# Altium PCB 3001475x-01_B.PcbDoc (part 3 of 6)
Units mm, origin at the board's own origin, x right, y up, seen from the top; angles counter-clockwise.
Board outline 335 x 91 mm, 12 copper layers (Top Layer, L2 GND, Layer 3, L4 GND, Layer 5, L6 PWR, L7 3V3, Layer 8, L9 GND, Layer 10, L11 GND, Bottom Layer), stack 1.59 mm thick; 339 components, 431 nets, 1732 pads, 1526 vias.
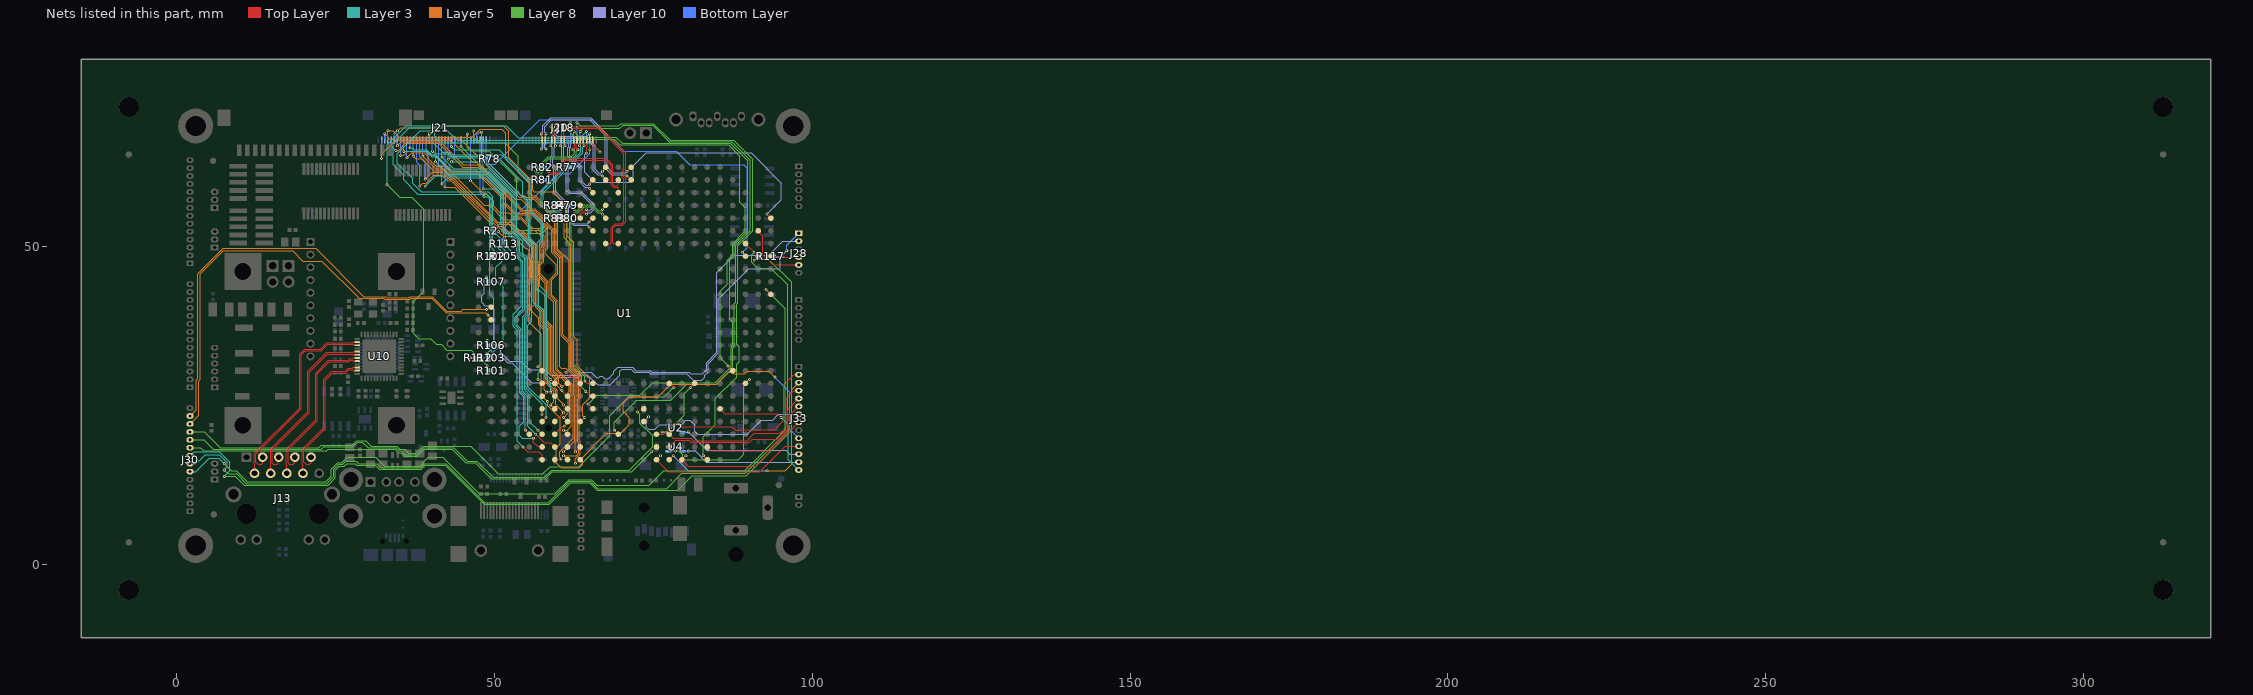
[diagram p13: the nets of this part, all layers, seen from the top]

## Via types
v1: diameter 0.45, hole 0.2, Top Layer to Bottom Layer, 1511 vias
v2: diameter 0.5, hole 0.2, Top Layer to Bottom Layer, 14 vias
v3: diameter 0.45/0.45/0.45/0.45/0.45/0.45/0.45/0.45/0.45/0.45/0.45/0.45 (per signal layer), hole 0.2, Top Layer to Bottom Layer, 1 vias

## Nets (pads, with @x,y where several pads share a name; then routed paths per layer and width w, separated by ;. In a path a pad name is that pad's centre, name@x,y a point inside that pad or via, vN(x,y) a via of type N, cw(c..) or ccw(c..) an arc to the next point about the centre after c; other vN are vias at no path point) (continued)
CSI1_D13: J33.2 U1.AB15 | length 30.2
  Top Layer w0.125: U1.AB15@75.5,20.5 75.538,20.462 76.546,20.462 77.996,21.913 79.087,21.913 79.288,21.712 87.288,21.712 87.875,21.125 89,21.125 89.062,21.187 94.062,21.187 95.552,22.677 95.552,28.302 97.125,29.875 J33.2@97.875,29.875
CSI1_D14: J33.3 U1.AD16 | length 34.2
  Top Layer w0.125: U1.AD16@77.5,16.5 v1(78.125,17.125)
  Layer 5 w0.125: v1(92.875,14.75) 95.75,14.75 96.75,15.75 96.75,27.5 J33.3@97.875,28.625
  Layer 10 w0.125: v1(78.125,17.125) 80.5,14.75 v1(92.875,14.75)
CSI1_D15: J33.4 U1.AB16 | length 26.7
  Top Layer w0.125: U1.AB16@77.5,20.5 78.132,19.868 80.882,19.868 81.25,19.5 89.75,19.5 90.875,20.625 94.875,20.625 95.875,21.625 95.875,26.125 97.125,27.375 J33.4@97.875,27.375
CSI1_D16: J33.5 U1.AC16 | length 25.5
  Top Layer w0.125: U1.AC16@77.5,18.5 78.538,19.538 80.671,19.538 80.958,19.25 90.125,19.25 90.552,19.677 94.427,19.677 96.125,21.375 96.125,24.375 J33.5@97.875,26.125
CSI1_D17: J33.6 U1.AC19 | length 18.8
  Top Layer w0.125: U1.AC19@83.5,18.5 84.132,17.868 92.993,17.868 96.375,21.25 96.375,23.375 J33.6@97.875,24.875
CSI1_D18: J33.7 U1.AA14 | length 30.4
  Top Layer w0.125: U1.AA14@73.5,22.5 v1(74.25,23.25)
  Layer 10 w0.125: v1(74.25,23.25) 73.875,22.875 73.875,21.625 74.25,21.25 75.25,21.25 76,22 79.413,22 80.125,22.712 80.75,22.712 81.5,21.962 81.5,21 82,20.5 89.75,20.5 91.962,22.712 93.75,22.712 94.663,23.625 J33.7@97.875,23.625
CSI1_D19: J33.8 U1.AD17 | length 22.5
  Top Layer w0.125: v1(80.125,17.125) U1.AD17@79.5,16.5 80.5,15.5 91,15.5 J33.8@97.875,22.375
CSI1_HSYNC: J33.12 U2.3 | length 19.7
  Layer 10 w0.125: v1(80.5,20.875) 83.375,18 95.875,18 96.5,17.375 J33.12@97.875,17.375
  Bottom Layer w0.125: U2.3@79.6,20.85 v1@80.475,20.85
CSI1_HSYNC/BTCFG2_3: U1.V18 U2.4 | length 11.3
  Top Layer w0.125: v1(80.875,27.875) U1.V18@81.5,28.5
  Layer 8 w0.125: v1(76.375,20.875) 77.25,20.875 79.875,23.5 79.875,26.875 v1(80.875,27.875)
  Bottom Layer w0.125: v1@76.4,20.85 U2.4@77.4,20.85
CSI1_MCLK: J33.10 R2.2 | length 99.1
  Layer 5 w0.125: v1(50.625,52.375) 51.375,51.625 53,51.625 54.875,49.75 55.125,49.75 55.5,49.375 55.5,38.125 57.375,36.25 57.375,26.625 v1(58.375,25.625) 58.375,25 60.375,23 60.375,19 59.75,18.375 59.75,16 60.5,15.25 63.375,15.25 63.875,15.75 63.875,16.875 67.625,20.625 69.896,20.625 71.25,21.979 71.25,23.125 70.25,24.125 70.25,25.375 71.25,26.375 75.75,26.375 77.75,28.375 84.875,28.375 86.75,30.25 87.375,30.25 87.625,30 89.375,30 89.75,30.375 93.25,30.375 v1(94.125,29.5)
  Bottom Layer w0.125: R2.2@50.105,52.375 v1(50.625,52.375) ; v1(94.125,29.5) 96.5,27.125 96.5,21.25 J33.10@97.875,19.875
CSI1_PIXCLK: J33.11 U1.AD15 | length 25.7
  Top Layer w0.125: v1(76.125,17.125) U1.AD15@75.5,16.5 77.375,14.625 91.75,14.625 95.75,18.625 J33.11@97.875,18.625
CSI1_RESET_N: J33.14 U1.Y20 | length 19.6
  Top Layer w0.125: U1.Y20@85.5,24.5 86.25,23.75 94.5,23.75 v1(95.125,23.125)
  Layer 3 w0.125: v1(95.125,23.125) 96.25,22 96.25,16.5 J33.14@97.875,14.875
CSI1_VSYNC: J33.13 U4.3 | length 19
  Layer 10 w0.125: v1(80.5,17.875) 81.625,17.875 82.462,17.038 82.462,16.954 83.292,16.125 J33.13@97.875,16.125
  Bottom Layer w0.125: U4.3@79.6,17.85 v1@80.475,17.85
CSI1_VSYNC/BTCFG2_4: U1.V22 U4.4 | length 26.1
  Top Layer w0.125: U1.V22@89.5,28.5 v1(90.125,29.125)
  Layer 8 w0.125: v1(78.5,17.875) 79,17.875 79.625,17.25 79.625,16.75 79.875,16.5 88.396,16.5 89.25,17.354 89.25,28.25 v1(90.125,29.125)
  Bottom Layer w0.125: U4.4@77.425,17.875 v1(78.5,17.875)
CSI_CLK0_N: J20.15 U1.B11 | length 17.1
  Top Layer w0.122: v1(58.875,68.875) 59.122,68.628 59.122,67.372 59,67.25 J20.15@59,66.8 ; v1(67,61.125) U1.B11@67.5,60.5
  Layer 10 w0.101: v1(58.875,68.875) 59.1,68.65 59.1,67.726 59.751,67.075 64.251,67.075 65.538,65.788 65.538,62.063 66.251,61.35 66.775,61.35 v1(67,61.125)
CSI_CLK0_P: J20.14 U1.A11 | length 16.6
  Top Layer w0.122: J20.14@59.5,66.8 59.5,67.25 59.377,67.373 59.377,68.628 v1(59.625,68.875) ; v1(67,61.875) U1.A11@67.5,62.5
  Layer 10 w0.101: v1(59.625,68.875) 59.4,68.65 59.4,67.85 59.875,67.375 64.375,67.375 65.838,65.912 65.838,62.187 66.375,61.65 66.775,61.65 v1(67,61.875)
CSI_D0_N: J20.12 U1.G12 | length 30.2
  Top Layer w0.122: J20.12@60.5,66.8 60.5,67.448 60.622,67.57 60.622,68.358 61.139,68.875 66.5,68.875 70.63,64.745 70.63,62.255 70.38,62.005 70.38,60.981 70.63,60.731 70.63,53.899 70.106,53.375 69.125,53.375 68.621,52.871 68.621,50.629 68.75,50.5 U1.G12@69.5,50.5
CSI_D0_P: J20.11 U1.G11 | length 29.3
  Top Layer w0.122: J20.11@61,66.8 61,67.448 60.877,67.57 60.877,68.253 61.245,68.62 66.394,68.62 70.375,64.639 70.375,62.361 70.125,62.111 70.125,60.875 70.375,60.625 70.375,54.005 70,53.63 69.019,53.63 68.366,52.977 68.366,50.629 68.237,50.5 U1.G11@67.5,50.5
CSI_D1_N: J20.18 U1.A13 | length 23.7
  Top Layer w0.122: v1(57.375,67.75) 57.5,67.625 J20.18@57.5,66.8 ; v1(70.875,61.875) U1.A13@71.5,62.5
  Layer 10 w0.101: v1(57.375,67.75) 57.6,67.975 57.6,68.999 58.851,70.25 65.125,70.25 67.75,67.625 67.75,62.5 68.6,61.65 70.65,61.65 v1(70.875,61.875)
CSI_D1_P: J20.17 U1.B13 | length 23.2
  Top Layer w0.122: J20.17@58,66.8 58,67.625 v1(58.125,67.75) ; v1(70.875,61.125) U1.B13@71.5,60.5
  Layer 10 w0.101: v1(58.125,67.75) 57.9,67.975 57.9,68.875 58.975,69.95 65.001,69.95 67.45,67.501 67.45,62.376 68.476,61.35 70.65,61.35 v1(70.875,61.125)
CSI_D2_N: R82.1 U1.B12 | length 17.7
  Top Layer w0.122: v1(58.5,61.875) 58.747,61.628 59.875,61.628 60.375,62.128 60.375,63.111 61.144,63.88 67.606,63.88 68.625,62.861 68.625,59.875 68.872,59.628 69.378,59.628 69.5,59.75 U1.B12@69.5,60.5
  Bottom Layer w0.122: R82.1@57.98,62.5 v1(58.5,61.875)
CSI_D2_P: R81.1 U1.C12 | length 17.7
  Top Layer w0.122: v1(58.5,61.125) 58.747,61.373 59.981,61.373 60.63,62.022 60.63,63.005 61.25,63.625 67.5,63.625 68.37,62.755 68.37,59.769 68.767,59.372 69.378,59.372 69.5,59.25 U1.C12@69.5,58.5
  Bottom Layer w0.122: R81.1@57.98,60.5 v1(58.5,61.125)
CSI_D3_N: R80.1 U1.E11 | length 7.1
  Top Layer w0.122: v1(67,55.125) U1.E11@67.5,54.5
  Layer 8 w0.101: v1(62.5,55.125) 62.725,55.35 63.149,55.35 64.124,56.325 65.251,56.325 66.226,55.35 66.775,55.35 v1(67,55.125)
  Bottom Layer w0.122: R80.1@61.98,54.5 v1(62.5,55.125)
CSI_D3_P: R79.1 U1.D11 | length 7.1
  Top Layer w0.122: v1(67,55.875) U1.D11@67.5,56.5
  Layer 8 w0.101: v1(62.5,55.875) 62.725,55.65 63.025,55.65 64,56.625 65.375,56.625 66.35,55.65 66.775,55.65 v1(67,55.875)
  Bottom Layer w0.122: R79.1@61.98,56.5 v1(62.5,55.875)
CSI_I2C_SCL: J20.2 R112.2 | length 88
  Top Layer w0.125: J20.2@65.5,66.8 65.5,66 v1(66.625,64.875)
  Layer 3 w0.125: v1(46.25,32.5) 48.875,32.5 51.375,35 51.375,43.6 50.25,44.725 50.25,46.75 51.25,47.75 51.25,49.125 49.75,50.625 49.75,57.875 49,58.625 38.5,58.625 37.125,60 37.125,60.75 34.75,63.125 34.75,64.625 38.375,68.25 40.25,68.25 40.625,67.875 40.625,67.25 41.5,66.375 65.125,66.375 v1(66.625,64.875)
  Bottom Layer w0.125: v1(46.25,32.5) R112.2@47.02,32.5
CSI_I2C_SDA: J20.3 R113.2 | length 22.5
  Top Layer w0.125: v1(65,65.25) J20.3@65,66.8
  Bottom Layer w0.125: R113.2@51.5,50.98 51.5,53 60,61.5 61.875,61.5 65,64.625 v1(65,65.25)
CSI_RESET_N: J20.4 U1.E24 | length 48.6
  Top Layer w0.125: v1(64.5,64.75) 64.5,65.5 64.625,65.625 64.625,66 64.5,66.125 J20.4@64.5,66.8 ; v1(92.875,55.125) U1.E24@93.5,54.5
  Layer 10 w0.125: v1(64.5,64.75) 64.25,64.5 64.25,61.75 65.875,60.125 71.25,60.125 71.875,60.75 71.875,62.75 73.875,64.75 90.375,64.75 95.125,60 95.125,57.375 v1(92.875,55.125)
CSID2_N: J20.8 R82.2 | length 11.3
  Top Layer w0.122: v1(62.375,65.25) 62.622,65.497 62.622,66.253 62.5,66.375 J20.8@62.5,66.8
  Layer 8 w0.101: v1(56.5,61.875) 56.725,61.65 57,61.65 57.375,62.025 57.375,63.049 58.451,64.125 62.125,64.125 62.6,64.6 62.6,65.025 v1(62.375,65.25)
  Bottom Layer w0.122: v1(56.5,61.875) R82.2@57.02,62.5
CSID2_P: J20.7 R81.2 | length 11.8
  Top Layer w0.122: J20.7@63,66.8 63,66.375 62.877,66.252 62.877,65.498 v1(63.125,65.25)
  Layer 8 w0.101: v1(56.5,61.125) 56.725,61.35 57.124,61.35 57.675,61.901 57.675,62.925 58.575,63.825 62.249,63.825 62.9,64.476 62.9,65.025 v1(63.125,65.25)
  Bottom Layer w0.122: v1(56.5,61.125) R81.2@57.02,60.5
CSID3_N: J20.6 R80.2 R83.2 | length 18.4
  Top Layer w0.122: v1(63.375,65.875) 63.5,66 J20.6@63.5,66.8
  Layer 3 w0.101: v1(60.5,55.125) 60.275,55.35 58.476,55.35 57.375,56.451 57.375,58.65 63.6,64.875 63.6,65.65 v1(63.375,65.875)
  Bottom Layer w0.122: R83.2@59.98,54.5 v1(60.5,55.125) R80.2@61.02,54.5
CSID3_P: J20.5 R79.2 R84.2 | length 17.9
  Top Layer w0.122: J20.5@64,66.8 64,66 v1(64.125,65.875)
  Layer 3 w0.101: v1(60.5,55.875) 60.275,55.65 58.6,55.65 57.675,56.575 57.675,58.526 63.9,64.751 63.9,65.65 v1(64.125,65.875)
  Bottom Layer w0.122: R84.2@59.98,56.5 v1(60.5,55.875) R79.2@61.02,56.5
DISP0_CLK: J21.27 U1.V9 | length 54.6
  Top Layer w0.125: v1(61.25,30.25) 62,29.5 62.5,29.5 U1.V9@63.5,28.5
  Layer 8 w0.125: v1(44.75,65.75) 51.75,58.75 51.75,54 53.625,52.125 57.5,52.125 58.5,53.125 58.5,53.875 59,54.375 60.875,54.375 61.375,53.875 61.375,50.75 61.75,50.375 61.75,30.75 v1(61.25,30.25)
  Bottom Layer w0.125: v1(44.75,65.75) J21.27@44.75,66.8
DISP0_CONTRAST: J21.32 U1.AD8 | length 63.2
  Top Layer w0.125: v1(60.875,17.125) U1.AD8@61.5,16.5
  Layer 5 w0.125: v1(48,68) 48,64.25 54.25,58 54.75,58 55,57.75 56.375,57.75 60,54.125 60,49.625 61.75,47.875 61.75,35.5 62.25,35 62.25,30.957 63.25,29.957 63.25,26.25 63.125,26.125 63.125,19.25 63.25,19.125 63.25,17.5 62.875,17.125 v1(60.875,17.125)
  Bottom Layer w0.125: J21.32@47.25,66.8 47.25,67.625 47.625,68 v1(48,68)
DISP0_DAT0: J21.2 U1.AC8 | length 76.3
  Top Layer w0.125: v1(60.875,17.75) U1.AC8@61.5,18.5
  Layer 5 w0.125: v1(32.25,63.875) 32.25,64.625 34.375,66.75 43.125,66.75 46.625,63.25 47.5,63.25 53.25,57.5 54.25,57.5 55.75,56 56.375,56 57.375,55 58.25,55 59.5,53.75 59.5,49.375 60.5,48.375 60.5,36 61.75,34.75 61.75,30.75 62.75,29.75 62.75,26.625 62.625,26.5 62.625,19.5 v1(60.875,17.75)
  Bottom Layer w0.125: v1(32.25,63.875) J21.2@32.25,66.8
DISP0_DAT1: J21.3 U1.AC9 | length 72.4
  Top Layer w0.125: v1(62.75,17.75) U1.AC9@63.5,18.5
  Layer 5 w0.125: v1(32.75,67.75) 33.5,67 44.625,67 53.875,57.75 54.625,57.75 54.875,57.5 56.25,57.5 59.75,54 59.75,49.5 60.75,48.5 60.75,36.125 62,34.875 62,30.854 63,29.854 63,26.5 62.875,26.375 62.875,19.375 62.75,19.25 v1(62.75,17.75)
  Bottom Layer w0.125: J21.3@32.75,66.8 v1(32.75,67.75)
DISP0_DAT2: J21.4 U1.AD9 | length 80
  Top Layer w0.125: v1(62.75,15.875) U1.AD9@63.5,16.5
  Layer 5 w0.125: v1(33.25,68.25) 34,68.25 35,67.25 46.5,67.25 47.75,68.5 51.125,68.5 51.75,67.875 51.75,63.75 55.5,60 55.5,58.5 56,58 56.5,58 57.864,56.636 58.364,56.636 61,54 61,51.375 62,50.375 62,35.625 62.5,35.125 62.5,31.061 63.5,30.061 63.5,26.125 63.375,26 63.375,19.5 63.5,19.375 63.5,17.375 62.75,16.625 v1(62.75,15.875)
  Bottom Layer w0.125: J21.4@33.25,66.8 v1(33.25,68.25)
DISP0_DAT3: J21.5 U1.AB8 | length 68.1
  Top Layer w0.125: v1(60.875,21.125) U1.AB8@61.5,20.5
  Layer 5 w0.125: v1(34.5,65.125) 34.875,65.125 36,66.25 41.25,66.25 45,62.5 47.375,62.5 54.375,55.5 56.125,55.5 59,52.625 59,49.125 60,48.125 60,45.979 60,45.771 59,44.771 59,42.354 59.875,41.479 59.875,30.729 62.229,28.375 62.25,28.375 62.25,26.875 62.125,26.75 62.125,21.75 61.5,21.125 v1(60.875,21.125)
  Bottom Layer w0.125: J21.5@33.75,66.8 33.75,65.875 v1(34.5,65.125)
DISP0_DAT4: J21.6 U1.AA9 | length 73.3
  Top Layer w0.125: U1.AA9@63.5,22.5 v1(64.125,23.125)
  Layer 5 w0.125: v1(34.75,68.25) 35.25,68.75 41.125,68.75 41.375,69 51.375,69 52.25,68.125 52.25,64 56,60.25 56,58.854 56.229,58.625 59.146,58.625 61.5,56.271 61.5,51.625 62.5,50.625 62.5,35.875 63,35.375 63,31.268 65,29.268 65,26.25 63.875,25.125 63.875,23.375 v1(64.125,23.125)
  Bottom Layer w0.125: J21.6@34.25,66.8 34.25,67.75 v1(34.75,68.25)
DISP0_DAT5: J21.7 U1.AD7 | length 71.3
  Top Layer w0.125: U1.AD7@59.5,16.5 v1(60.5,16.625)
  Layer 5 w0.125: v1(34.75,65.875) 35.375,66.5 41.5,66.5 45.125,62.875 47.375,62.875 54.5,55.75 56.25,55.75 59.25,52.75 59.25,49.25 60.25,48.25 60.25,31.125 60.5,30.875 61.25,30.875 62.5,29.625 62.5,26.75 62.375,26.625 62.375,19.875 60.25,17.75 60.25,16.875 v1(60.5,16.625)
  Bottom Layer w0.125: v1(34.75,65.875) J21.7@34.75,66.8
DISP0_DAT6: J21.8 U1.AB7 | length 67.4
  Top Layer w0.125: U1.AB7@59.5,20.5 60.125,21.125 60.75,21.75 v1(61,21.75)
  Layer 5 w0.125: v1(35.25,64.375) 35.75,64.375 36.375,65 39.5,65 40,64.5 40.625,64.5 43,62.125 47.125,62.125 51.75,57.5 51.75,56.875 53.375,55.25 56,55.25 58.375,52.875 58.375,49.75 58,49.375 58,48.875 59.75,47.125 59.75,45.875 58.75,44.875 58.75,42.25 59.625,41.375 59.625,30.625 62,28.25 62,27 61.875,26.875 61.875,22.625 v1(61,21.75)
  Bottom Layer w0.125: v1(35.25,64.375) J21.8@35.25,66.8
DISP0_DAT7: J21.9 U1.AC7 | length 64.9
  Top Layer w0.125: v1(56.5,20.5) 57.875,19.125 58.875,19.125 U1.AC7@59.5,18.5
  Layer 3 w0.125: v1(35.75,65) 39.25,65 40.125,64.125 40.75,64.125 43.25,61.625 49,61.625 52.75,57.875 52.75,52.25 54,51 54,49.104 55,48.104 55,39.5 54.5,39 54.5,27.25 55.25,26.5 55.25,21.75 v1(56.5,20.5)
  Bottom Layer w0.125: v1(35.75,65) J21.9@35.75,66.8
DISP0_DAT8: J21.10 U1.AA8 | length 63.6
  Top Layer w0.125: v1(60.875,23.125) U1.AA8@61.5,22.5
  Layer 5 w0.125: v1(36.25,64) 37,64.75 39,64.75 39.625,64.125 39.625,63.875 40.875,62.625 42.125,62.625 43.125,61.625 47.25,61.625 51.5,57.375 51.5,56.75 53,55.25 53.25,55 55.875,55 58.125,52.75 58.125,49.875 57.75,49.5 57.75,47.625 57.25,47.125 57.25,45.75 58.5,44.5 58.5,42.125 59.375,41.25 59.375,30.5 61.75,28.125 61.75,27.25 61.625,27.125 61.625,23.875 v1(60.875,23.125)
  Bottom Layer w0.125: v1(36.25,64) J21.10@36.25,66.8
DISP0_DAT9: J21.11 U1.AB6 | length 60.4
  Top Layer w0.125: v1(56.875,21.125) U1.AB6@57.5,20.5
  Layer 3 w0.125: v1(36.75,65.5) 37.125,65.5 37.375,65.25 39.375,65.25 40.25,64.375 40.875,64.375 43.375,61.875 49.146,61.875 53,58.021 53,52.375 54.5,50.875 54.5,49 55.25,48.25 55.25,39.375 54.75,38.875 54.75,27.5 55.5,26.75 55.5,22.5 v1(56.875,21.125)
  Bottom Layer w0.125: v1(36.75,65.5) J21.11@36.75,66.8
DISP0_DAT10: J21.12 U1.Y8 | length 55.6
  Top Layer w0.125: v1(60.875,25.125) U1.Y8@61.5,24.5
  Layer 5 w0.125: v1(37.25,64.25) 37.625,63.875 38.578,63.875 40.5,61.953 42.047,61.953 43.125,60.875 43.5,60.875 50.5,53.875 52.625,53.875 53.875,52.625 54.375,52.625 56.75,50.25 56.75,47.75 56.5,47.5 56.5,45.375 57,44.875 57,40.729 57.75,39.979 57.75,38.125 58.625,37.25 58.625,30.125 59.604,29.146 59.604,27.729 59.875,27.457 59.875,27.043 59.875,26.125 v1(60.875,25.125)
  Bottom Layer w0.125: v1@37.25,64.375 J21.12@37.25,66.8
DISP0_DAT11: J21.13 U1.Y7 | length 58.4
  Top Layer w0.125: v1(58.875,25.125) U1.Y7@59.5,24.5
  Layer 5 w0.125: v1(38.25,59.5) 38.75,60 39.25,60 40.5,61.25 41.75,61.25 42.625,60.375 43.25,60.375 50.375,53.25 51.125,53.25 52,52.375 53.375,52.375 53.625,52.125 54.146,52.125 56.25,50.021 56.25,48.125 56,47.875 56,45.125 56.5,44.625 56.5,40.5 57.25,39.75 57.25,37.875 58.125,37 58.125,28.5 59.375,27.25 59.375,25.625 v1(58.875,25.125)
  Bottom Layer w0.125: J21.13@37.75,66.8 37.75,63.25 38.25,62.75 v1(38.25,59.5)
DISP0_DAT12: J21.14 U1.AA7 | length 59.4
  Top Layer w0.125: U1.AA7@59.5,22.5 v1(60.875,23.875)
  Layer 5 w0.125: v1(39.125,60.625) 40.203,61.703 41.797,61.703 42.875,60.625 43.375,60.625 50.5,53.5 52.625,53.5 53.75,52.375 54.25,52.375 56.5,50.125 56.5,47.875 56.25,47.625 56.25,45.25 56.75,44.75 56.75,40.625 57.5,39.875 57.5,38 58.375,37.125 58.375,28.604 59.625,27.354 59.625,27.146 59.625,25.125 v1(60.875,23.875)
  Bottom Layer w0.125: J21.14@38.25,66.8 38.25,64.125 39.125,63.25 v1(39.125,60.625)
DISP0_DAT13: J21.15 U1.W8 | length 53.8
  Top Layer w0.125: v1(60.625,27.375) U1.W8@61.5,26.5
  Layer 5 w0.125: v1(38.75,64.25) 40.75,62.25 42.125,62.25 43.25,61.125 43.75,61.125 48.375,56.5 49.25,56.5 51.5,54.25 53,54.25 53.125,54.375 54.125,54.375 55.875,52.625 56.375,52.625 57.5,51.5 57.5,50 57.25,49.75 57.25,47.875 56.75,47.375 56.75,45.5 58,44.25 58,38.25 58.875,37.375 58.875,30.25 59.875,29.25 59.875,28.125 v1(60.625,27.375)
  Bottom Layer w0.125: v1@38.75,64.375 J21.15@38.75,66.8
DISP0_DAT14: J21.16 U1.AC6 | length 67.3
  Top Layer w0.125: v1(56.125,19.875) 56.125,19.25 56.875,18.5 U1.AC6@57.5,18.5
  Layer 3 w0.125: v1(39.125,59.5) 40.75,61.125 48.75,61.125 51.5,58.375 51.5,52.646 53.5,50.646 53.5,48.75 54.5,47.75 54.5,40.25 53.25,39 53.25,37.625 54,36.875 54,27 54.625,26.375 54.625,22.5 53.875,21.75 53.875,20.375 54.375,19.875 v1(56.125,19.875)
  Bottom Layer w0.125: v1(39.125,59.5) 39.625,60 39.625,64.5 39.25,64.875 J21.16@39.25,66.8
DISP0_DAT15: J21.17 U1.W7 | length 56.1
  Top Layer w0.125: v1(58.875,27.125) U1.W7@59.5,26.5
  Layer 3 w0.125: v1(39.75,67.75) 39.75,67 41.875,64.875 42.875,64.875 43.25,64.5 51.125,64.5 55.625,60 55.625,55.375 57.375,53.625 57.375,51.25 56.75,50.625 56.75,43.5 58,42.25 58,29.375 58.875,28.5 v1(58.875,27.125)
  Bottom Layer w0.125: J21.17@39.75,66.8 v1(39.75,67.75)
DISP0_DAT16: J21.18 U1.V6 | length 51.7
  Top Layer w0.125: v1(56.875,29.125) U1.V6@57.5,28.5
  Layer 3 w0.125: v1(40.25,65) 40.625,64.625 42.625,64.625 43,64.25 50.375,64.25 54.5,60.125 54.5,58.125 55.25,57.375 55.25,54.375 55.625,54 55.625,51.25 56.5,50.375 56.5,43.396 57,42.896 57,40.75 57.75,40 57.75,31 56.875,30.125 v1(56.875,29.125)
  Bottom Layer w0.125: v1(40.25,65) J21.18@40.25,66.8
DISP0_DAT17: J21.19 U1.AB5 | length 57
  Top Layer w0.125: v1(54.875,21.125) U1.AB5@55.5,20.5
  Layer 3 w0.125: v1(40.75,63.375) 42.75,61.375 48.875,61.375 51.75,58.5 51.75,52.75 53.75,50.75 53.75,49 54.75,48 54.75,40.125 53.587,38.962 53.587,37.663 54.25,37 54.25,27.125 54.875,26.5 v1(54.875,21.125)
  Bottom Layer w0.125: v1(40.75,63.375) J21.19@40.75,66.8
DISP0_DAT18: J21.20 U1.AD6 | length 64.5
  Top Layer w0.125: v1(54.5,18.5) 55.25,17.75 57,17.75 57.5,17.25 U1.AD6@57.5,16.5
  Layer 3 w0.125: v1(41.75,59.875) 42.75,60.875 48.646,60.875 51.25,58.271 51.25,52.5 51.75,52 51.75,50.125 54.25,47.625 54.25,40.625 53,39.375 53,37.5 53.625,36.875 53.625,19.375 v1(54.5,18.5)
  Bottom Layer w0.125: J21.20@41.25,66.8 41.25,62.75 41.75,62.25 v1(41.75,59.875)
DISP0_DAT19: J21.21 U1.Y6 | length 54.3
  Top Layer w0.125: v1(57.5,23.625) U1.Y6@57.5,24.5
  Layer 3 w0.125: v1(41.75,64.125) 43.625,62.25 49.125,62.25 53.25,58.125 53.25,52.5 55.587,50.163 55.587,39.337 55,38.75 55,27.75 57.5,25.25 v1(57.5,23.625)
  Bottom Layer w0.125: v1(41.75,64.125) J21.21@41.75,66.8
DISP0_DAT20: J21.22 U1.W6 | length 50.4
  Top Layer w0.125: U1.W6@57.5,26.5 v1(58.25,27.125)
  Layer 5 w0.125: v1(42.25,59.375) 43.75,59.375 50.125,53 50.75,53 51.625,52.125 53.25,52.125 53.5,51.875 54,51.875 56,49.875 56,48.375 55.75,48.125 55.75,45 56.25,44.5 56.25,40.875 55.75,40.375 55.75,40 57,38.75 57,37.75 57.875,36.875 57.875,27.5 v1(58.25,27.125)
  Bottom Layer w0.125: v1(42.25,59.375) J21.22@42.25,66.8
DISP0_DAT21: J21.23 U1.U6 | length 46.3
  Top Layer w0.125: v1(56.875,31.125) U1.U6@57.5,30.5
  Layer 3 w0.125: v1(42.75,63.75) 43,64 48.25,64 55,57.25 55,54.25 55.375,53.875 55.375,51.125 56.125,50.375 56.125,41.25 57.25,40.125 57.25,31.5 v1(56.875,31.125)
  Bottom Layer w0.125: v1(42.75,63.75) J21.23@42.75,66.8
DISP0_DAT22: J21.24 U1.V7 | length 49.5
  Top Layer w0.125: v1(58.875,29.125) U1.V7@59.5,28.5
  Layer 3 w0.125: v1(43.25,65.75) 43.75,65.25 50.75,65.25 55.875,60.125 55.875,55.5 57.625,53.75 57.625,51.125 57.125,50.625 57.125,43.875 58.25,42.75 58.25,29.75 v1(58.875,29.125)
  Bottom Layer w0.125: v1(43.25,65.75) J21.24@43.25,66.8
DISP0_DAT23: J21.25 U1.AA6 | length 54.5
  Top Layer w0.125: U1.AA6@57.5,22.5 v1(58.125,23.125)
  Layer 3 w0.125: v1(43.25,63.375) 48.375,63.375 53.5,58.25 53.5,52.625 55.837,50.288 55.837,39.954 55.912,39.879 55.912,38.301 55.25,37.638 55.25,28 58.125,25.125 v1(58.125,23.125)
  Bottom Layer w0.125: v1(43.25,63.375) 43.75,63.875 J21.25@43.75,66.8
DISP0_DRDY: J21.31 U1.V10 | length 60.6
  Top Layer w0.125: v1(64.25,28.875) 64.625,28.5 U1.V10@65.5,28.5
  Layer 8 w0.125: v1(46.75,68.25) 46.75,67.25 47.625,66.375 51.625,66.375 53.75,64.25 53.75,61.875 55.5,60.125 55.5,53.125 55.75,52.875 57.25,52.875 57.75,53.375 57.75,54.375 59.913,56.538 60.962,56.538 61.5,56 61.5,54.875 62.087,54.288 62.087,51.101 62.375,50.813 62.375,31.5 64.25,29.625 v1(64.25,28.875)
  Bottom Layer w0.125: J21.31@46.75,66.8 v1(46.75,68.25)
DISP0_HSYNC: J21.29 U1.W10 | length 62.1
  Top Layer w0.125: v1(64.375,27.25) U1.W10@65.5,26.5
  Layer 8 w0.125: v1(45.75,67.75) 45.75,65.625 46.25,65.125 49.125,65.125 53.5,60.75 53.5,52.979 53.854,52.625 57.375,52.625 58,53.25 58,54.25 60.038,56.288 60.859,56.288 61.25,55.896 61.25,54.75 61.837,54.163 61.837,50.997 62.125,50.71 62.125,31.25 63.75,29.625 63.75,27.875 v1(64.375,27.25)
  Bottom Layer w0.125: J21.29@45.75,66.8 v1(45.75,67.75)
DISP0_I2C_SCL: J21.33 R103.2 | length 35.7
  Layer 3 w0.125: v1(48.375,57.875) 48.875,57.875 49.25,57.5 49.25,42.625 49.875,42 49.875,34.25 v1(48.875,33.25)
  Bottom Layer w0.125: J21.33@47.75,66.8 47.75,58.5 v1(48.375,57.875) ; R103.2@48.875,32.645 v1(48.875,33.25)
DISP0_I2C_SDA: J21.34 R105.2 | length 22.1
  Layer 3 w0.125: v1(48.25,59.125) 50.043,59.125 51,58.168 51,53.75 50.125,52.875 50.125,52.125 51.25,51 51.25,49.875 v1(52.25,48.875)
  Bottom Layer w0.125: v1(48.25,59.125) J21.34@48.25,66.8 ; R105.2@51.52,48.875 v1(52.25,48.875)
DISP0_IRQ_N: J21.35 R78.2 U1.H22 | length 65
  Top Layer w0.125: v1(89,49.125) U1.H22@89.5,48.5
  Bottom Layer w0.125: R78.2@48.75,63.895 J21.35@48.75,66.8 ; R78.2@48.77,63.875 48.77,63.23 49,63 50.125,63 57.125,70 65.375,70 70.375,65 78.625,65 80.75,62.875 89.25,62.875 89.75,62.375 89.75,49.875 v1(89,49.125)
DISP0_VSYNC: J21.30 U1.V8 | length 48.6
  Top Layer w0.125: v1(60.625,28) U1.V8@61.5,28.5
  Layer 5 w0.125: v1(46.25,60.375) 48.25,58.375 48.625,58.375 49.875,57.125 49.875,56.375 50.875,55.375 52.375,55.375 53,54.75 54.125,54.75 56,52.875 56.625,52.875 57.875,51.625 57.875,50 57.5,49.625 57.5,47.75 57,47.25 57,45.625 58.25,44.375 58.25,38.375 59.125,37.5 59.125,30.375 60.125,29.375 60.125,28.5 v1(60.625,28)
  Bottom Layer w0.125: v1(46.25,60.375) J21.30@46.25,66.8
DSI_CLK0_N: J18.7 U1.E10 | length 18.1
  Top Layer w0.122: v1(64.875,53.875) U1.E10@65.5,54.5
  Layer 10 w0.101: v1(59.625,65.875) 59.4,65.65 59.4,64.251 59.175,64.026 59.175,62.999 59.675,62.499 59.675,58.624 61.675,56.624 61.675,54.575 62.6,53.65 64.65,53.65 v1(64.875,53.875)
  Bottom Layer w0.122: J18.7@59.5,66.8 59.5,66 v1(59.625,65.875)
DSI_CLK0_P: J18.6 U1.F10 | length 18.6
  Top Layer w0.122: v1(64.875,53.125) U1.F10@65.5,52.5
  Layer 10 w0.101: v1(58.875,65.875) 59.1,65.65 59.1,64.375 58.875,64.15 58.875,62.875 59.375,62.375 59.375,58.5 61.375,56.5 61.375,54.451 62.476,53.35 64.65,53.35 v1(64.875,53.125)
  Bottom Layer w0.122: v1(58.875,65.875) 59,66 J18.6@59,66.8
DSI_CONTRAST: J18.13 U1.Y10 | length 90.5
  Top Layer w0.125: v1(64.75,25.25) U1.Y10@65.5,24.5
  Layer 8 w0.125: v1(62.5,68.125) 63.375,67.25 69.125,67.25 70.125,66.25 87.125,66.25 89.875,63.5 89.875,52.5 87.75,50.375 87.75,48.625 87,47.875 87,38.625 87.5,38.125 87.5,34.5 87.25,34.25 87.25,31.125 84.75,28.625 74.875,28.625 72.875,26.625 66.125,26.625 v1(64.75,25.25)
  Bottom Layer w0.125: J18.13@62.5,66.8 v1(62.5,68.125)
DSI_D0_N: J18.4 U1.C10 | length 16
  Top Layer w0.122: v1(65,59.125) U1.C10@65.5,58.5
  Layer 10 w0.101: v1(58.125,65.375) 57.95,65.55 57.95,66.026 58.374,66.45 61.501,66.45 61.7,66.251 61.7,65.749 61.537,65.586 61.537,64.213 63.325,62.425 63.325,60.276 64.251,59.35 64.775,59.35 v1(65,59.125)
  Bottom Layer w0.122: J18.4@58,66.8 58,66.073 57.881,65.954 57.881,65.619 v1(58.125,65.375)
DSI_D0_P: J18.3 U1.B10 | length 16.6
  Top Layer w0.122: v1(65,59.875) U1.B10@65.5,60.5
  Layer 10 w0.101: v1(57.375,65.375) 57.55,65.55 57.55,66.05 58.25,66.75 61.625,66.75 62,66.375 62,65.625 61.837,65.462 61.837,64.337 63.625,62.549 63.625,60.4 64.375,59.65 64.775,59.65 v1(65,59.875)
  Bottom Layer w0.122: v1(57.375,65.375) 57.619,65.619 57.619,65.954 57.5,66.073 J18.3@57.5,66.8
DSI_D1_N: J18.10 U1.E9 | length 17.4
  Top Layer w0.122: U1.E9@63.5,54.5 63.5,55.25 63.619,55.369 64.256,55.369 v1(64.5,55.125)
  Layer 10 w0.101: v1(61.125,65.875) 60.9,65.65 60.9,63.35 61.625,62.625 61.625,58.924 61.874,58.675 63.624,58.675 65.675,56.624 65.675,55.901 65.124,55.35 64.725,55.35 v1(64.5,55.125)
  Bottom Layer w0.122: J18.10@61,66.8 61,66 v1(61.125,65.875)
DSI_D1_P: J18.9 U1.D9 | length 16.9
  Top Layer w0.122: U1.D9@63.5,56.5 63.5,55.766 63.635,55.631 64.256,55.631 v1(64.5,55.875)
  Layer 10 w0.101: v1(60.375,65.875) 60.6,65.65 60.6,63.226 61.325,62.501 61.325,58.8 61.75,58.375 63.5,58.375 65.375,56.5 65.375,56.025 65,55.65 64.725,55.65 v1(64.5,55.875)
  Bottom Layer w0.122: v1(60.375,65.875) 60.5,66 J18.9@60.5,66.8
DSI_I2C_SCL: J18.17 R101.2 | length 83.5
  Layer 8 w0.125: v1(33.125,59.75) 35.125,57.75 37,57.75 38.875,55.875 38.875,43 37.25,41.375 37.25,36.375 38.125,35.5 40,35.5 40.875,34.625 41.625,34.625 42.5,33.75 46.375,33.75 v1(48.875,31.25)
  Layer 3 w0.125: v1(33.125,59.75) 33.125,66 36.125,69 51.875,69 53.75,67.125 63.5,67.125 v1(64.5,68.125)
  Bottom Layer w0.125: v1(48.875,31.25) 48.875,30.645 R101.2@49.02,30.5 ; J18.17@64.5,66.8 v1(64.5,68.125)
DSI_I2C_SDA: J18.18 R102.2 | length 65.3
  Layer 3 w0.125: v1(50.375,49) 49.5,49.875 49.5,57.625 48.837,58.288 37.962,58.288 35.75,60.5 35.75,61.25 34.087,62.913 34.087,66.212 36.625,68.75 42.125,68.75 44.125,66.75 64,66.75 v1(65,67.75)
  Bottom Layer w0.125: R102.2@49.5,48.98 v1@50.355,48.98 ; J18.18@65,66.8 v1(65,67.75)
DSI_IRQ_N: J18.12 R77.2 U1.U21 | length 73.3
  Top Layer w0.125: v1(86.75,31.25) U1.U21@87.5,30.5
  Layer 8 w0.125: v1(62,69.5) 62,67.875 63,66.875 68.875,66.875 69.75,66 86.875,66 88.625,64.25 88.625,57 89.5,56.125 89.5,52.5 87.5,50.5 87.5,48.75 86.625,47.875 86.625,44.125 85.5,43 85.5,32.5 v1(86.75,31.25)
  Bottom Layer w0.125: R77.2@61.875,62.605 61.875,65.625 62,65.75 J18.12@62,66.8 v1(62,69.5)
DSI_PWR_EN: J18.15 U1.AB12 | length 88.9
  Top Layer w0.125: v1(68.875,21.125) U1.AB12@69.5,20.5
  Layer 8 w0.125: v1(63.5,68.125) 64,68.625 69.75,68.625 70.25,69.125 74.875,69.125 77.5,66.5 87.375,66.5 90.25,63.625 90.25,52.5 88,50.25 88,41.25 87.75,41 87.75,34.25 87.5,34 87.5,30.875 85,28.375 80.25,28.375 77.75,25.875 72.375,25.875 68.875,22.375 v1(68.875,21.125)
  Bottom Layer w0.125: J18.15@63.5,66.8 v1(63.5,68.125)
DSI_RESET_N: J18.14 U1.AD19 | length 84
  Top Layer w0.125: v1(82.875,17.125) U1.AD19@83.5,16.5
  Layer 8 w0.125: v1(63,69.5) 63.5,69 69.5,69 69.875,69.375 75,69.375 77.625,66.75 87.625,66.75 90.625,63.75 90.625,52.5 88.25,50.125 88.25,41.125 88.125,41 88.125,34.625 88.5,34.25 88.5,31.875 88.125,31.5 88.125,29.5 84.75,26.125 84.75,22 82.875,20.125 v1(82.875,17.125)
  Bottom Layer w0.125: J18.14@63,66.8 v1(63,69.5)
ETH_TXRXA_N: J13.3 U10.3 | length 31.6
  Top Layer w0.122: J13.3@13.54,16.89 13.54,15.915 13.375,15.75 12.875,15.75 12.5,16.125 12.5,17.375 19.625,24.5 19.625,33 20.25,33.625 22.753,33.625 23.75,34.622 27.689,34.622 27.811,34.5 U10.3@28.425,34.5
ETH_TXRXA_P: J13.2 U10.2 | length 31.6
  Top Layer w0.122: J13.2@12.27,14.35 12.27,15.855 12.245,15.88 12.245,17.481 19.37,24.606 19.37,33.106 20.144,33.88 22.647,33.88 23.644,34.877 27.689,34.877 27.811,35 U10.2@28.425,35
ETH_TXRXB_N: J13.5 U10.6 | length 27.5
  Top Layer w0.122: J13.5@16,16.81 16,15.875 15.875,15.75 15.25,15.75 15.08,15.92 15.08,18.094 20.88,23.894 20.88,30.269 23.733,33.122 27.689,33.122 27.811,33 U10.6@28.425,33
ETH_TXRXB_P: J13.4 U10.5 | length 27.5
  Top Layer w0.122: J13.4@14.825,14.365 14.825,18.2 20.625,24 20.625,30.375 23.627,33.377 27.689,33.377 27.811,33.5 U10.5@28.425,33.5
ETH_TXRXC_N: J13.7 U10.8 | length 25.3
  Top Layer w0.122: J13.7@18.62,16.89 18.62,15.995 18.375,15.75 17.75,15.75 17.55,15.95 17.55,18.064 22.13,22.644 22.13,30.019 23.986,31.875 27.128,31.875 27.375,32.123 27.689,32.123 27.811,32 U10.8@28.425,32
ETH_TXRXC_P: J13.6 U10.7 | length 25.3
  Top Layer w0.122: J13.6@17.375,14.375 J13.6@17.35,14.35 17.35,15.65 17.25,15.75 17.25,18.125 21.875,22.75 21.875,30.125 23.88,32.13 27.022,32.13 27.269,32.378 27.689,32.378 27.811,32.5 U10.7@28.425,32.5
ETH_TXRXD_N: J13.9 U10.11 | length 22.3
  Top Layer w0.122: J13.9@21.16,16.89 21.16,16.035 20.875,15.75 20.375,15.75 20,16.125 20,18.014 23.38,21.394 23.38,29.019 24.486,30.125 26.611,30.125 27.108,30.622 27.689,30.622 27.811,30.5 U10.11@28.425,30.5
ETH_TXRXD_P: J13.8 U10.10 | length 22.3
  Top Layer w0.122: J13.8@19.89,14.35 19.89,15.624 19.745,15.769 19.745,18.12 23.125,21.5 23.125,29.125 24.38,30.38 26.505,30.38 27.002,30.877 27.689,30.877 27.811,31 U10.10@28.425,31
EXP_GPIO_0: J30.6 U1.L24 | length 131.2
  Top Layer w0.125: v1(92.75,43.25) U1.L24@93.5,42.5
  Layer 8 w0.125: v1(7.5,15.875) 8.625,14.75 9.375,14.75 11.125,13 23.5,13 24.375,13.875 24.375,15.021 25.354,16 26,16 26.875,16.875 31.375,16.875 32.75,15.5 38.25,15.5 39.625,16.875 41.875,16.875 47.625,11.125 59.5,11.125 61.75,13.375 65.25,13.375 66.125,12.5 74.375,12.5 76.625,14.75 89.354,14.75 95.788,21.184 95.788,40.212 v1(92.75,43.25)
  Layer 3 w0.125: J30.6@2.125,14.625 3,14.625 5.125,16.75 6.625,16.75 v1(7.5,15.875)
EXP_GPIO_1: J30.7 U1.G22 | length 142.6
  Top Layer w0.125: U1.G22@89.5,50.5 v1(90.875,49.125)
  Layer 8 w0.125: v1(7.5,14.875) 8.125,14.25 9.5,14.25 11,12.75 23.625,12.75 24.75,13.875 24.75,15 25.5,15.75 26.125,15.75 26.625,16.25 28.25,16.25 28.625,15.875 31.5,15.875 32.125,15.25 38.354,15.25 38.979,15.875 42.375,15.875 48.5,9.75 58.5,9.75 61.875,13.125 64.896,13.125 65.104,13.125 66.266,11.962 77.087,11.962 79.5,14.375 89.5,14.375 96.125,21 96.125,44 93.5,46.625 91.375,46.625 90.462,47.538 90.462,48.712 v1(90.875,49.125)
  Layer 3 w0.125: J30.7@2.125,15.875 3.125,15.875 4.5,17.25 6.75,17.25 8,16 8,15.375 v1(7.5,14.875)
EXP_GPIO_2: J30.8 U1.H23 | length 142.3
  Top Layer w0.125: v1(90.875,47.875) U1.H23@91.5,48.5
  Layer 8 w0.125: v1(7.5,13.875) 9.25,13.875 10.625,12.5 23.875,12.5 25,13.625 25,14.875 25.625,15.5 26.375,15.5 26.75,15.875 28.125,15.875 28.375,15.625 31.25,15.625 31.875,15 38.457,15 39.082,15.625 42.25,15.625 48.375,9.5 58.625,9.5 62,12.875 65,12.875 66.163,11.712 78.837,11.712 81.125,14 89.625,14 96.75,21.125 96.75,44.375 93,48.125 91.125,48.125 v1(90.875,47.875)
  Layer 3 w0.125: J30.8@2.125,17.125 2.75,17.75 6.75,17.75 8.375,16.125 8.375,14.75 v1(7.5,13.875)
EXP_GPIO_3: J30.9 U1.AC15 | length 78.6
  Top Layer w0.125: v1(74.75,17.75) U1.AC15@75.5,18.5
  Layer 8 w0.125: J30.9@2.125,18.375 3.75,18.375 4.25,17.875 23.625,17.875 23.875,18.125 34.375,18.125 34.875,17.625 35.25,17.625 35.875,17 37.875,17 39,18.125 43.375,18.125 45.5,16 47,16 49.538,13.462 57.962,13.462 59.125,14.625 71.625,14.625 v1(74.75,17.75)
EXP_GPIO_4: J30.10 U1.Y14 | length 86.7
  Top Layer w0.125: v1(72.5,24) U1.Y14@73.5,24.5
  Layer 8 w0.125: J30.10@2.125,19.625 4.25,19.625 5.75,18.125 22.75,18.125 23.125,18.5 27.75,18.5 28.5,19.25 29.25,19.25 30.125,18.375 34.5,18.375 35,17.875 35.375,17.875 35.979,17.271 35.979,17.25 37.75,17.25 38.875,18.375 43.625,18.375 45.75,16.25 47.25,16.25 49.788,13.712 57.838,13.712 59,14.875 71.25,14.875 74.875,18.5 74.875,20.25 72.875,22.25 72.875,23.625 v1(72.5,24)
EXP_GPIO_5: J30.11 U1.V16 | length 89.2
  Top Layer w0.125: U1.V16@77.5,28.5 v1(78.25,27.875)
  Layer 8 w0.125: J30.11@2.125,20.875 4.375,20.875 6.875,18.375 22.375,18.375 22.75,18.75 27.625,18.75 28.375,19.5 29.75,19.5 30.625,18.625 34.625,18.625 35.125,18.125 35.875,18.125 36.5,17.5 37.646,17.5 38.771,18.625 46.25,18.625 50.625,14.25 57.625,14.25 58.75,15.375 63.25,15.375 68.125,20.25 68.125,23.375 71.125,26.375 76.75,26.375 v1(78.25,27.875)
EXP_GPIO_6: J30.12 U1.N2 | length 76.3
  Top Layer w0.125: v1(49,39.25) U1.N2@49.5,38.5
  Layer 5 w0.125: J30.12@2.125,22.125 3.5,23.5 3.5,28.875 3.75,29.125 3.75,45.771 7.354,49.375 18.25,49.375 19.875,47.75 22.875,47.75 28.712,41.913 32.625,41.913 32.788,41.75 36.712,41.75 36.875,41.913 40.109,41.913 42.396,39.625 42.604,39.625 48.625,39.625 v1(49,39.25)
EXP_GPIO_7: J30.13 U1.M2 | length 75.1
  Top Layer w0.125: v1(48.75,40.125) U1.M2@49.5,40.5
  Layer 5 w0.125: J30.13@2.125,23.375 3.125,24.375 3.125,29 3.375,29.25 3.375,45.75 7.375,49.75 21.875,49.75 29.462,42.163 32.875,42.163 33.038,42 36.5,42 36.663,42.163 40.212,42.163 42.5,39.875 44.75,39.875 45,40.125 v1(48.75,40.125)
EXP_I2C_GPIO: J28.5 U1.F23 | length 10.4
  Top Layer w0.125: U1.F23@91.5,52.5 92.25,51.75 92.25,48.75 93.875,47.125 J28.5@97.875,47.125
EXP_I2C_IRQ_N: J28.4 R117.2 U1.H24 | length 8.2
  Top Layer w0.125: U1.H24@93.5,48.5 95.5,48.5 95.625,48.375 J28.4@97.875,48.375
  Bottom Layer w0.125: R117.2@94.105,48.375 J28.4@97.875,48.375
EXP_I2C_SCL: J28.1 R106.2 | length 73.6
  Layer 10 w0.125: v1(48.875,35.25) 48.875,34.25 50.25,32.875 51,32.875 52.125,31.75 52.75,31.75 55.875,28.625 59.125,28.625 60,29.5 63.125,29.5 63.5,29.875 64.625,29.875 66.25,28.25 68.25,28.25 69.75,29.75 69.75,30.375 70.125,30.75 71.5,30.75 72,30.25 74.25,30.25 74.5,30 80.25,30 81.25,29 82.625,29 83.125,29.5 83.125,29.75 83.625,30.25 83.625,31.625 85.25,33.25 85.25,41.75 90,46.5 95,46.5 95,48.375 v1(96,49.375)
  Bottom Layer w0.125: v1(48.875,35.25) 48.875,34.645 R106.2@49.02,34.5 ; v1(96,49.375) 96,50.25 J28.1@97.875,52.125
EXP_I2C_SDA: J28.2 R107.2 | length 81.9
  Layer 10 w0.125: v1(48.75,45.25) 48.438,44.938 48.438,42.687 48,42.25 48,41.25 48.5,40.75 49.375,40.75 50,40.125 50,34.625 51,33.625 51,33.375 52.375,32 54.125,32 55.5,30.625 58,30.625 58.875,29.75 63,29.75 63.5,30.25 65.25,30.25 66.125,29.375 66.375,29.375 66.625,29.625 67,29.625 67.375,29.25 67.875,29.25 68.75,30.125 68.75,30.375 69.375,31 71.75,31 72.25,30.5 74.5,30.5 74.75,30.25 80.625,30.25 80.875,30 82.75,30 83.375,30.625 83.375,31.75 85,33.375 85,45.875 87.75,48.625 93.125,48.625 95.375,50.875 J28.2@97.875,50.875
  Bottom Layer w0.125: v1(48.75,45.25) 48.75,44.77 R107.2@49.02,44.5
